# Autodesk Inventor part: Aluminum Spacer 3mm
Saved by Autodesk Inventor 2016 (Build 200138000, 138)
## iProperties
Created: 2016-01
Part Number: Aluminum Spacer 3mm
Material: Generic
Document SubType Name: Modeling
Designer: John
Density: 1 g/cm^3
Appearance: Default
Author: John
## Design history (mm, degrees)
feature "CHAMFER1"
body "Solid1"
